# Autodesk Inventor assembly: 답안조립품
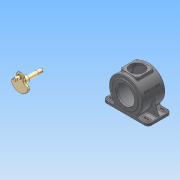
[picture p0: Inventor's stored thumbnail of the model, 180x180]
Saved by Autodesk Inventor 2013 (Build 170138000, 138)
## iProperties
Created: 2015-06
Part Number: 답안조립품
Document SubType Name: Assembly
Designer: Administrator
Author: Administrator
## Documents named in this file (3)
- C:\Users\Administrator\Desktop\450606V1015\답안조립품.iam
- C:\Users\Administrator\Desktop\450606V1015\본체.ipt
- C:\Users\Administrator\Desktop\450606V1015\메인 크랭크 축-구동부.ipt
